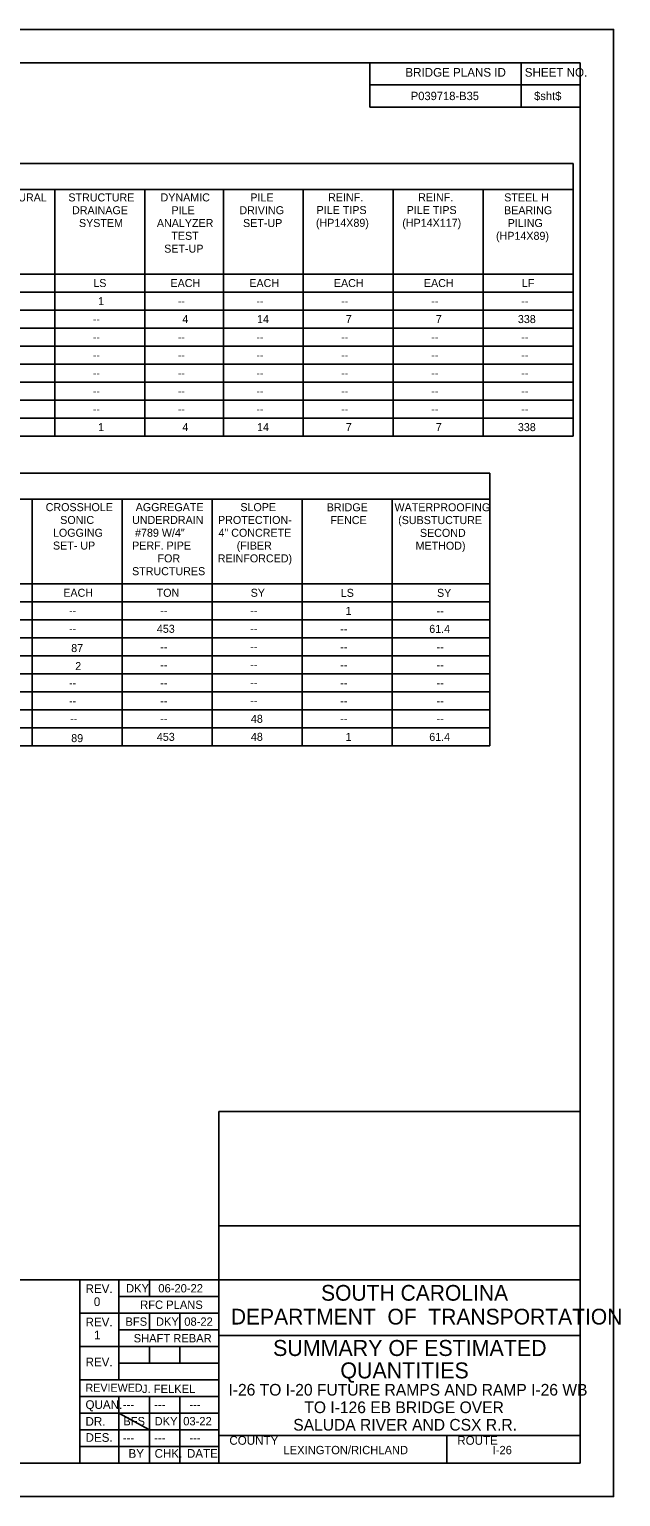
# Model space of a CAD drawing. Extents: x -125.5 to -89.4, y -5.1 to 16.9.
# Drawn here: x -98.29 to -89.43, y -5.07 to 16.93 of the extents above; entities that cross this region are included whole.
import ezdxf

# ---------------------------------------------------------------- set-up
doc = ezdxf.new("R2010")
doc.units = 0
for name, color, linetype in [('BR_BORDER LINES', 7, 'Continuous'), ('BR_TABLE LINES', 7, 'Continuous'), ('BR_TEXT', 7, 'Continuous'), ('Level 31', 7, 'Continuous')]:
    doc.layers.add(name, color=color, linetype=linetype)

msp = doc.modelspace()

# ---------------------------------------------------------------- linework, layer by layer
at = {"layer": 'BR_BORDER LINES'}
for p, q in [((-90.033, 16.434), (-123.699, 16.434)), ((-93.186, 15.767), (-93.186, 16.434)), ((-90.919, 15.767), (-90.919, 16.434)), ((-90.033, -4.566), (-90.033, 16.434)), ((-93.186, 16.104), (-90.033, 16.104)), ((-90.919, 16.104), (-90.033, 16.104)), ((-90.033, 15.767), (-93.186, 15.767)), ((-95.45, -4.566), (-95.45, 0.71)), ((-95.45, 0.71), (-90.033, 0.71)), ((-95.45, -1.004), (-90.033, -1.004)), ((-102.899, -1.816), (-97.534, -1.816)), ((-97.534, -4.566), (-97.534, -1.816)), ((-97.534, -1.816), (-90.033, -1.816)), ((-96.95, -1.816), (-96.95, -3.316)), ((-96.492, -2.066), (-96.492, -1.816)), ((-96.95, -2.066), (-95.45, -2.066)), ((-97.534, -2.316), (-95.45, -2.316)), ((-96.492, -2.566), (-96.492, -2.316)), ((-96.034, -2.566), (-96.034, -2.316)), ((-96.95, -2.566), (-95.45, -2.566)), ((-97.534, -2.816), (-95.45, -2.816)), ((-96.492, -3.066), (-96.492, -2.816)), ((-96.034, -3.066), (-96.034, -2.816)), ((-95.45, -2.649), (-95.45, -2.649)), ((-95.45, -2.649), (-90.033, -2.649)), ((-96.95, -3.066), (-95.45, -3.066)), ((-97.534, -3.316), (-95.45, -3.316)), ((-97.534, -3.566), (-95.45, -3.566)), ((-96.95, -3.566), (-96.95, -4.566)), ((-96.492, -3.566), (-96.492, -4.566)), ((-96.034, -3.566), (-96.034, -4.566)), ((-97.534, -3.816), (-95.45, -3.816)), ((-97.534, -4.066), (-95.45, -4.066)), ((-95.45, -4.149), (-90.033, -4.149)), ((-95.353, -4.149), (-90.033, -4.149)), ((-92.033, -4.566), (-92.033, -4.149)), ((-97.534, -4.316), (-95.45, -4.316)), ((-123.699, -4.566), (-90.033, -4.566))]:
    msp.add_line(p, q, dxfattribs=at)
at = {"layer": 'BR_TABLE LINES'}
for p, q in [((-123.551, 14.923), (-90.138, 14.923)), ((-90.138, 14.923), (-90.138, 10.835)), ((-123.551, 14.533), (-90.138, 14.533)), ((-97.911, 14.533), (-97.911, 10.835)), ((-96.561, 14.533), (-96.561, 10.835)), ((-95.382, 14.533), (-95.382, 10.835)), ((-94.188, 14.533), (-94.188, 10.835)), ((-92.838, 14.533), (-92.838, 10.835)), ((-91.488, 14.533), (-91.488, 10.835)), ((-123.551, 13.265), (-90.138, 13.265)), ((-123.551, 12.995), (-90.138, 12.995)), ((-90.138, 12.725), (-123.551, 12.725)), ((-90.138, 12.455), (-123.551, 12.455)), ((-90.138, 12.185), (-123.551, 12.185)), ((-90.138, 11.915), (-123.551, 11.915)), ((-90.138, 11.645), (-123.551, 11.645)), ((-90.138, 11.375), (-123.551, 11.375)), ((-90.138, 11.105), (-123.551, 11.105)), ((-90.138, 10.835), (-123.551, 10.835)), ((-123.551, 10.28), (-91.389, 10.28)), ((-91.389, 10.28), (-91.389, 6.192)), ((-123.551, 9.89), (-91.389, 9.89)), ((-98.251, 9.889), (-98.251, 6.192)), ((-96.901, 9.889), (-96.901, 6.192)), ((-95.551, 9.889), (-95.551, 6.192)), ((-94.201, 9.888), (-94.201, 6.192)), ((-92.851, 9.888), (-92.851, 6.192)), ((-123.551, 8.622), (-91.389, 8.622)), ((-123.551, 8.352), (-91.389, 8.352)), ((-91.389, 8.082), (-123.551, 8.082)), ((-91.389, 7.812), (-123.551, 7.812)), ((-91.389, 7.542), (-123.551, 7.542)), ((-91.389, 7.272), (-123.551, 7.272)), ((-91.389, 7.002), (-123.551, 7.002)), ((-91.389, 6.732), (-123.551, 6.732)), ((-91.389, 6.462), (-123.551, 6.462)), ((-91.389, 6.192), (-123.551, 6.192))]:
    msp.add_line(p, q, dxfattribs=at)
at = {"layer": 'Level 31'}
for p, q in [((-92.742, -3.09), (-92.742, -3.09)), ((-96.95, -3.816), (-96.492, -4.066))]:
    msp.add_line(p, q, dxfattribs=at)
msp.add_lwpolyline([(-125.533, -5.066), (-89.533, -5.066), (-89.533, 16.934), (-125.533, 16.934)], close=True, dxfattribs=at)

# ---------------------------------------------------------------- texts
at = {"layer": 'BR_TEXT'}
for s, height, p in [('BRIDGE PLANS ID', 0.13, (-92.654, 16.224)), ('SHEET NO.', 0.13, (-90.864, 16.224)), ('P039718-B35', 0.125, (-92.573, 15.873)), ('$sht$', 0.125, (-90.724, 15.873)), ('STRUCTURAL ', 0.12, (-99.109, 14.354)), ('STRUCTURE ', 0.12, (-97.707, 14.354)), ('DYNAMIC ', 0.12, (-96.325, 14.354)), ('PILE', 0.12, (-94.979, 14.354)), ('REINF. ', 0.12, (-93.813, 14.357)), ('REINF. ', 0.12, (-92.463, 14.357)), ('STEEL H ', 0.12, (-91.172, 14.354)), ('DRAINAGE ', 0.12, (-97.652, 14.162)), ('SYSTEM', 0.12, (-97.548, 13.97)), ('ANALYZER ', 0.12, (-96.38, 13.97)), ('PILE ', 0.12, (-96.161, 14.162)), ('DRIVING', 0.12, (-95.143, 14.162)), ('SET-UP', 0.12, (-95.088, 13.97)), ('(HP14X89)', 0.12, (-93.995, 13.973)), ('PILE TIPS ', 0.12, (-93.985, 14.165)), ('(HP14X117)', 0.12, (-92.7, 13.973)), ('PILE TIPS ', 0.12, (-92.635, 14.165)), ('BEARING ', 0.12, (-91.175, 14.162)), ('PILING ', 0.12, (-91.12, 13.97)), ('TEST ', 0.12, (-96.163, 13.778)), ('(HP14X89)', 0.12, (-91.295, 13.778)), ('SET-UP', 0.12, (-96.27, 13.586)), ('LS', 0.12, (-97.333, 13.07)), ('EACH', 0.12, (-96.176, 13.07)), ('EACH', 0.12, (-94.994, 13.07)), ('EACH', 0.12, (-93.726, 13.07)), ('EACH', 0.12, (-92.376, 13.07)), ('LF', 0.12, (-90.907, 13.07)), ('1', 0.12, (-97.261, 12.8)), ('--', 0.12, (-96.067, 12.8)), ('--', 0.12, (-94.888, 12.8)), ('--', 0.12, (-93.617, 12.8)), ('--', 0.12, (-92.267, 12.8)), ('--', 0.12, (-90.917, 12.8)), ('--', 0.12, (-97.34, 12.53)), ('4', 0.12, (-95.998, 12.53)), ('14', 0.12, (-94.878, 12.53)), ('7', 0.12, (-93.548, 12.53)), ('7', 0.12, (-92.198, 12.53)), ('338', 0.12, (-90.967, 12.53)), ('--', 0.12, (-97.34, 12.26)), ('--', 0.12, (-96.067, 12.26)), ('--', 0.12, (-94.888, 12.26)), ('--', 0.12, (-93.617, 12.26)), ('--', 0.12, (-92.267, 12.26)), ('--', 0.12, (-90.917, 12.26)), ('--', 0.12, (-97.34, 11.99)), ('--', 0.12, (-96.067, 11.99)), ('--', 0.12, (-94.888, 11.99)), ('--', 0.12, (-93.617, 11.99)), ('--', 0.12, (-92.267, 11.99)), ('--', 0.12, (-90.917, 11.99)), ('--', 0.12, (-97.34, 11.72)), ('--', 0.12, (-96.067, 11.72)), ('--', 0.12, (-94.888, 11.72)), ('--', 0.12, (-93.617, 11.72)), ('--', 0.12, (-92.267, 11.72)), ('--', 0.12, (-90.917, 11.72)), ('--', 0.12, (-97.34, 11.45)), ('--', 0.12, (-96.067, 11.45)), ('--', 0.12, (-94.888, 11.45)), ('--', 0.12, (-93.617, 11.45)), ('--', 0.12, (-92.267, 11.45)), ('--', 0.12, (-90.917, 11.45)), ('--', 0.12, (-97.34, 11.18)), ('--', 0.12, (-96.067, 11.18)), ('--', 0.12, (-94.888, 11.18)), ('--', 0.12, (-93.617, 11.18)), ('--', 0.12, (-92.267, 11.18)), ('--', 0.12, (-90.917, 11.18)), ('1', 0.12, (-97.261, 10.91)), ('4', 0.12, (-95.998, 10.91)), ('14', 0.12, (-94.878, 10.91)), ('7', 0.12, (-93.548, 10.91)), ('7', 0.12, (-92.198, 10.91)), ('338', 0.12, (-90.967, 10.91)), ('CROSSHOLE ', 0.12, (-98.047, 9.71)), ('AGGREGATE ', 0.12, (-96.697, 9.71)), ('SLOPE ', 0.12, (-95.128, 9.71)), ('BRIDGE ', 0.12, (-93.833, 9.708)), ('WATERPROOFING ', 0.12, (-92.817, 9.708)), ('SONIC ', 0.12, (-97.829, 9.518)), ('UNDERDRAIN ', 0.12, (-96.752, 9.518)), ('PROTECTION- ', 0.12, (-95.463, 9.518)), ('FENCE', 0.12, (-93.778, 9.516)), ('(SUBSTUCTURE', 0.12, (-92.762, 9.516)), ('SET- UP', 0.12, (-97.938, 9.134)), ('LOGGING ', 0.12, (-97.938, 9.326)), ('PERF. PIPE ', 0.12, (-96.751, 9.134)), ('#789 W/4" ', 0.12, (-96.707, 9.326)), ('4" CONCRETE ', 0.12, (-95.456, 9.326)), ('(FIBER ', 0.12, (-95.183, 9.134)), ('METHOD)', 0.12, (-92.501, 9.132)), ('SECOND ', 0.12, (-92.436, 9.324)), ('FOR ', 0.12, (-96.37, 8.942)), ('REINFORCED)', 0.12, (-95.467, 8.942)), ('STRUCTURES', 0.12, (-96.752, 8.75)), ('EACH', 0.12, (-97.783, 8.426)), ('TON', 0.12, (-96.383, 8.426)), ('SY', 0.12, (-94.974, 8.426)), ('LS', 0.12, (-93.623, 8.425)), ('SY', 0.12, (-92.18, 8.425)), ('--', 0.12, (-97.697, 8.156)), ('--', 0.12, (-96.33, 8.156)), ('--', 0.12, (-94.98, 8.157)), ('1', 0.12, (-93.551, 8.155)), ('--', 0.12, (-92.187, 8.155)), ('--', 0.12, (-97.697, 7.886)), ('453', 0.12, (-96.38, 7.886)), ('--', 0.12, (-94.98, 7.887)), ('--', 0.12, (-93.63, 7.885)), ('61.4', 0.12, (-92.296, 7.885)), ('87', 0.12, (-97.664, 7.597)), ('--', 0.12, (-96.33, 7.616)), ('--', 0.12, (-94.98, 7.617)), ('--', 0.12, (-93.63, 7.615)), ('--', 0.12, (-92.187, 7.615)), ('2', 0.12, (-97.604, 7.327)), ('--', 0.12, (-96.33, 7.346)), ('--', 0.12, (-94.98, 7.347)), ('--', 0.12, (-93.63, 7.345)), ('--', 0.12, (-92.187, 7.345)), ('--', 0.12, (-97.697, 7.076)), ('--', 0.12, (-96.33, 7.076)), ('--', 0.12, (-94.98, 7.077)), ('--', 0.12, (-93.63, 7.075)), ('--', 0.12, (-92.187, 7.075)), ('--', 0.12, (-97.697, 6.806)), ('--', 0.12, (-96.33, 6.806)), ('--', 0.12, (-94.98, 6.807)), ('--', 0.12, (-93.63, 6.805)), ('--', 0.12, (-92.187, 6.805)), ('48', 0.12, (-94.97, 6.536)), ('--', 0.12, (-97.68, 6.537)), ('453', 0.12, (-96.38, 6.266)), ('--', 0.12, (-96.33, 6.537)), ('48', 0.12, (-94.97, 6.266)), ('--', 0.12, (-93.63, 6.537)), ('1', 0.12, (-93.551, 6.265)), ('61.4', 0.12, (-92.296, 6.265)), ('--', 0.12, (-92.187, 6.537)), ('89', 0.12, (-97.664, 6.247)), ('REV.', 0.13, (-97.449, -2.013)), ('DKY', 0.125, (-96.842, -2.004)), ('06-20-22', 0.125, (-96.358, -2.004)), ('SOUTH CAROLINA', 0.23587, (-93.918, -2.128)), ('0', 0.13, (-97.325, -2.208)), ('RFC PLANS', 0.125, (-96.63, -2.251)), ('REV.', 0.13, (-97.449, -2.513)), ('BFS', 0.125, (-96.851, -2.504)), ('DKY', 0.125, (-96.394, -2.504)), ('08-22', 0.125, (-95.969, -2.504)), ('DEPARTMENT  OF  TRANSPORTATION', 0.23587, (-95.271, -2.485)), ('1', 0.13, (-97.323, -2.708)), ('SHAFT REBAR', 0.125, (-96.728, -2.753)), ('SUMMARY OF ESTIMATED', 0.24, (-94.638, -2.957)), ('REV.', 0.13, (-97.449, -3.111)), ('QUANTITIES', 0.24, (-93.629, -3.293)), ('REVIEWED', 0.12, (-97.45, -3.493)), ('J. FELKEL', 0.125, (-96.603, -3.512)), ('I-26 TO I-20 FUTURE RAMPS AND RAMP I-26 WB', 0.175, (-95.307, -3.551)), ('QUAN.', 0.13, (-97.45, -3.751)), ('---', 0.125, (-96.889, -3.747)), ('---', 0.125, (-96.419, -3.747)), ('---', 0.125, (-95.893, -3.747)), ('TO I-126 EB BRIDGE OVER', 0.175, (-94.169, -3.814)), ('DR.', 0.13, (-97.45, -4.003)), ('BFS', 0.125, (-96.883, -3.997)), ('DKY', 0.125, (-96.414, -3.997)), ('03-22', 0.125, (-95.985, -3.997)), ('SALUDA RIVER AND CSX R.R.', 0.175, (-94.335, -4.076)), ('DES.', 0.13, (-97.449, -4.244)), ('COUNTY', 0.13, (-95.293, -4.288)), ('ROUTE', 0.13, (-91.876, -4.288)), ('---', 0.125, (-96.889, -4.247)), ('BY', 0.13, (-96.805, -4.484)), ('---', 0.125, (-96.419, -4.247)), ('CHK.', 0.13, (-96.414, -4.483)), ('DATE', 0.13, (-95.929, -4.483)), ('---', 0.125, (-95.893, -4.247)), ('LEXINGTON/RICHLAND', 0.12499, (-94.481, -4.43)), ('I-26', 0.125, (-91.345, -4.43))]:
    msp.add_text(s, height=height, dxfattribs=at).set_placement(p)

doc.saveas('drawing.dxf')
